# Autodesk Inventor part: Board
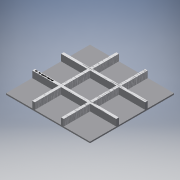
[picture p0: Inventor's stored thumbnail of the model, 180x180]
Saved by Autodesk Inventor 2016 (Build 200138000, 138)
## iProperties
Created: 2017-05
Part Number: Board
Material: Glass
Document SubType Name: Modeling
Designer: 8643301
Density: 2.18 g/cm^3
Appearance: Default
Author: 8643301
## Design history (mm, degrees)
sketch "Sketch1"
  geometry: L1 (-40.64, -40.64)-(40.64, -40.64); L2 (40.64, -40.64)-(40.64, 40.64); L3 (40.64, 40.64)-(-40.64, 40.64); L4 (-40.64, 40.64)-(-40.64, -40.64); L5 (-40.64, -40.64)-(40.64, 40.64); L6 (40.64, -40.64)-(-40.64, 40.64); 1 further point
  constraints: 12 end point, 2 midpoint, 2 parallel, 1 horizontal, 1 perpendicular
  dimensions: "d0" = 81.28 distance of L3.end L2.end; "d1" = 81.28 distance of L2.end L1.end
extrude "Extrusion1" new body sketch "Sketch1" distance "d2" = 1.27; taper "d3" = 0 deg
sketch "Sketch2"
  geometry: L1 (40.64, 40.64)-(-40.64, 40.64) reference; L2 (15.24, 40.64)-(12.7, 40.64); L3 (12.7, 40.64)-(12.7, -40.64); L4 (12.7, -40.64)-(15.24, -40.64); L5 (15.24, -40.64)-(15.24, 40.64); L6 (40.64, -40.64)-(40.64, 40.64) reference; L7 (-12.7, 40.64)-(-15.24, 40.64); L8 (-15.24, 40.64)-(-15.24, -40.64); L9 (-15.24, -40.64)-(-12.7, -40.64); L10 (-12.7, -40.64)-(-12.7, 40.64)
  constraints: 16 end point, 4 parallel, 2 horizontal, 2 perpendicular, 2 point on line
  dimensions: "d13" = 2.54 distance of L4.end L3.end; "d14" = 81.28 distance of L3.end L2.end; "d15" = 25.4 distance between parallel lines of L5 L6; "d16" = 2.54 distance of L9.end L8.end; "d17" = 81.28 distance of L8.end L7.end; "d18" = 25.4 distance between parallel lines of L10 L3
extrude "Extrusion2" join sketch "Sketch2" distance "d11" = 6.35; taper "d12" = 0 deg
workplane "Work Plane1"
mirror "Mirror1"
sketch "Sketch3"
  geometry: L1 (-39.134, -13.18)-(26.869, -13.18); L2 (26.869, -13.18)-(26.869, -14.096); L3 (26.869, -14.096)-(-39.134, -14.096); L4 (-39.134, -14.096)-(-39.134, -13.18); L5 (12.7, -15.24)-(12.7, -40.64) reference; L6 (12.7, -40.64)-(15.24, -40.64) reference; L7 (15.24, -40.64)-(15.24, -15.24) reference; L8 (40.64, -15.24)-(15.24, -15.24) reference; L9 (40.64, -12.7)-(40.64, -15.24) reference; L10 (15.24, -12.7)-(40.64, -12.7) reference; L11 (15.24, -12.7)-(15.24, 12.7) reference; L12 (40.64, 12.7)-(15.24, 12.7) reference; L13 (40.64, 15.24)-(40.64, 12.7) reference; L14 (15.24, 15.24)-(40.64, 15.24) reference; L15 (15.24, 15.24)-(15.24, 40.64) reference; L16 (15.24, 40.64)-(12.7, 40.64) reference; L17 (12.7, 40.64)-(12.7, 15.24) reference; L18 (-12.7, 15.24)-(12.7, 15.24) reference; L19 (-12.7, 15.24)-(-12.7, 40.64) reference; L20 (-12.7, 40.64)-(-15.24, 40.64) reference; L21 (-15.24, 40.64)-(-15.24, 15.24) reference; L22 (-40.64, 15.24)-(-15.24, 15.24) reference; L23 (-40.64, 12.7)-(-40.64, 15.24) reference; L24 (-15.24, 12.7)-(-40.64, 12.7) reference; L25 (-15.24, 12.7)-(-15.24, -12.7) reference; L26 (-40.64, -12.7)-(-15.24, -12.7) reference; L27 (-40.64, -15.24)-(-40.64, -12.7) reference; L28 (-15.24, -15.24)-(-40.64, -15.24) reference; L29 (-15.24, -15.24)-(-15.24, -40.64) reference; L30 (-15.24, -40.64)-(-12.7, -40.64) reference; L31 (-12.7, -40.64)-(-12.7, -15.24) reference; L32 (12.7, -15.24)-(-12.7, -15.24) reference; L33 (-12.7, -12.7)-(12.7, -12.7) reference; L34 (-12.7, -12.7)-(-12.7, 12.7) reference; L35 (12.7, 12.7)-(-12.7, 12.7) reference; L36 (12.7, 12.7)-(12.7, -12.7) reference; 1 further point
  constraints: 2 other
emboss "Emboss1" sketch "Sketch3" dims "d3" = 0, "d19" = 0.254, "d20" = 0
body "Solid1"
node "Projected Loop1"
